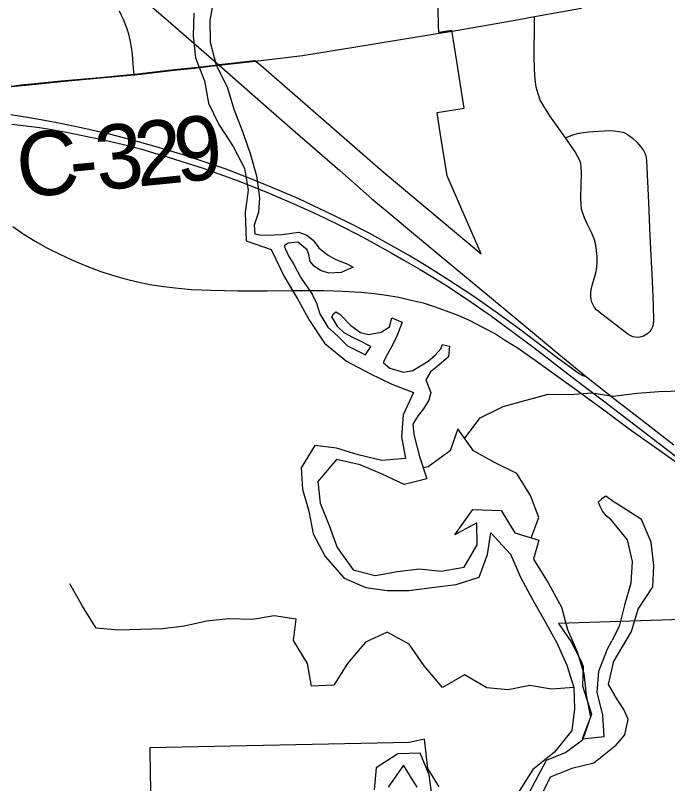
# Model space of a CAD drawing. Extents: x -6.4 to 34, y -4.2 to 22.
# Drawn here: x 4.489 to 5.066, y 17.606 to 18.286 of the extents above; entities that cross this region are included whole.
import ezdxf

# ---------------------------------------------------------------- set-up
doc = ezdxf.new("R2010")
doc.units = 0
for name, color, linetype in [('GM_X_Corporation', 7, 'Continuous'), ('GM_X_County_Road', 7, 'Continuous'), ('GM_X_County_Road_Text', 7, 'Continuous'), ('GM_X_Interchange_Ramps', 7, 'Continuous'), ('GM_X_Major_River', 7, 'Continuous'), ('GM_X_Minor_River', 7, 'Continuous'), ('GM_X_State_Route', 7, 'Continuous'), ('GM_X_Township_Road', 7, 'Continuous')]:
    doc.layers.add(name, color=color, linetype=linetype)

msp = doc.modelspace()

# ---------------------------------------------------------------- linework, layer by layer
at = {"layer": 'GM_X_Corporation'}
for points in [[(4.48506, 18.22318), (4.49382, 18.22417), (4.5149, 18.22629), (4.52916, 18.22763), (4.56388, 18.23083), (4.5937, 18.23365), (4.59436, 18.23371), (4.62916, 18.23774), (4.64724, 18.23961), (4.66596, 18.24174), (4.66901, 18.24211), (4.70069, 18.24566), (4.7064, 18.24128), (4.81426, 18.1471), (4.86666, 18.10342), (4.90117, 18.07465), (4.87091, 18.14362), (4.86521, 18.17986), (4.86209, 18.19978), (4.88602, 18.2036), (4.8825, 18.22601), (4.88132, 18.23356), (4.87661, 18.26351), (4.87515, 18.27234), (4.86948, 18.27132), (4.86354, 18.27045), (4.86347, 18.27676), (4.86282, 18.30664)], [(5.09729, 17.75149), (4.96968, 17.74738), (4.98078, 17.73099), (4.98912, 17.71503), (4.99128, 17.70933), (4.99082, 17.69215), (4.99887, 17.66701), (4.99089, 17.64415), (4.99042, 17.64379), (4.97618, 17.63304), (4.95872, 17.62611), (4.94349, 17.59773)], [(4.86379, 17.6026), (4.85389, 17.6191), (4.85082, 17.64485), (4.83992, 17.64244), (4.83759, 17.64193), (4.60765, 17.63721), (4.60768, 17.63599), (4.60811, 17.61377), (4.60858, 17.59005)]]:
    msp.add_lwpolyline(points, dxfattribs=at)
at = {"layer": 'GM_X_County_Road'}
for points in [[(4.87535, 18.27179), (4.93128, 18.28156), (4.94833, 18.28464), (4.98994, 18.29219)], [(4.70089, 18.24511), (4.74295, 18.25028), (4.79019, 18.25779), (4.86392, 18.26993)], [(4.86392, 18.26993), (4.86968, 18.27076), (4.87535, 18.27179)], [(4.64744, 18.23906), (4.66615, 18.24119), (4.66921, 18.24155), (4.70089, 18.24511)], [(4.5939, 18.23309), (4.59455, 18.23316), (4.62936, 18.23718), (4.64744, 18.23906)], [(4.49803, 18.22402), (4.5151, 18.22574), (4.52935, 18.22707), (4.56408, 18.23027), (4.5939, 18.23309)], [(4.48526, 18.22262), (4.49402, 18.22362), (4.49803, 18.22402)]]:
    msp.add_lwpolyline(points, dxfattribs=at)
at = {"layer": 'GM_X_Interchange_Ramps'}
for points in [[(4.5939, 18.23309), (4.59338, 18.2389), (4.59227, 18.25121), (4.59138, 18.25761), (4.59032, 18.2637), (4.58909, 18.26913), (4.58761, 18.2739), (4.58605, 18.27818), (4.58441, 18.28197), (4.58276, 18.28554), (4.58088, 18.28929)], [(4.99428, 17.96579), (4.99122, 17.96667), (4.98955, 17.96737), (4.98796, 17.96827), (4.96968, 17.9815), (4.93518, 18.00788), (4.91354, 18.02355), (4.89366, 18.0374), (4.87351, 18.05084), (4.85377, 18.06322), (4.83692, 18.07335), (4.81982, 18.08299), (4.80181, 18.09279), (4.78405, 18.10201), (4.76515, 18.11132), (4.73958, 18.12318), (4.71672, 18.1329), (4.69723, 18.14097), (4.67437, 18.14971), (4.65686, 18.15589), (4.63717, 18.16227), (4.61336, 18.16943), (4.59124, 18.17564), (4.57199, 18.18057), (4.54848, 18.18581), (4.5257, 18.1906), (4.5049, 18.1944), (4.48467, 18.19754)], [(4.48554, 18.18936), (4.49837, 18.18799), (4.50995, 18.18639), (4.52101, 18.1846), (4.53384, 18.18224), (4.54665, 18.17973), (4.56675, 18.17554), (4.58312, 18.17172), (4.59938, 18.16742), (4.61014, 18.16432), (4.62325, 18.16039), (4.63513, 18.1567), (4.65586, 18.15003), (4.66469, 18.147), (4.67698, 18.14254), (4.68744, 18.13852), (4.70825, 18.13025), (4.73519, 18.11888), (4.75225, 18.11129), (4.76239, 18.10654), (4.77691, 18.09937), (4.79183, 18.09166), (4.80337, 18.08553), (4.82134, 18.07558), (4.83265, 18.06907), (4.8472, 18.06068), (4.85846, 18.05403), (4.869, 18.0474), (4.88816, 18.03462), (4.91012, 18.01933), (4.92376, 18.00953), (4.94769, 17.99167), (4.9817, 17.96551), (5.00939, 17.94442), (5.0272, 17.93086), (5.08129, 17.88937)]]:
    msp.add_lwpolyline(points, dxfattribs=at)
at = {"layer": 'GM_X_Major_River'}
for p, q in [((5.00758, 17.85731), (5.00462, 17.85468)), ((5.00462, 17.85468), (5.00643, 17.85049)), ((5.01153, 17.85994), (5.00758, 17.85731)), ((5.01879, 17.85477), (5.01153, 17.85994)), ((5.00643, 17.85049), (5.00856, 17.84645)), ((5.00856, 17.84645), (5.01086, 17.84349)), ((5.01086, 17.84349), (5.01454, 17.84082)), ((5.01454, 17.84082), (5.01862, 17.83591))]:
    msp.add_line(p, q, dxfattribs=at)
for points in [[(4.6645, 18.30086), (4.66075, 18.28104), (4.66114, 18.26207), (4.66649, 18.24168), (4.67636, 18.22253), (4.68208, 18.20253), (4.68968, 18.18295), (4.69653, 18.16336), (4.70224, 18.14373), (4.70493, 18.12405)], [(4.64659, 18.28757), (4.64625, 18.26744), (4.64817, 18.24812), (4.65617, 18.22779), (4.65961, 18.20812), (4.66872, 18.18896), (4.68163, 18.16949), (4.6915, 18.15034), (4.69493, 18.13105), (4.69231, 18.11125), (4.69295, 18.08619), (4.71519, 18.07844), (4.72682, 18.05466), (4.7386, 18.0348), (4.74923, 18.01566), (4.76253, 17.99544), (4.7818, 17.97953), (4.80249, 17.96858), (4.82201, 17.95913), (4.8411, 17.95194), (4.83204, 17.93201), (4.83055, 17.91262), (4.83398, 17.89333), (4.81318, 17.89175)], [(4.70493, 18.12405), (4.70405, 18.1115), (4.70012, 18.10003), (4.70066, 18.09245), (4.70522, 18.09141), (4.71129, 18.09116), (4.72454, 18.09182), (4.73965, 18.09366), (4.7469, 18.09116), (4.7523, 18.08672), (4.75736, 18.07999), (4.76507, 18.0737), (4.77235, 18.06968), (4.78305, 18.06535), (4.78765, 18.0628), (4.77714, 18.05801), (4.76617, 18.0574), (4.75892, 18.0599), (4.75316, 18.06358), (4.74966, 18.06768), (4.74839, 18.07411), (4.74717, 18.07826), (4.7387, 18.08491), (4.73038, 18.08397), (4.72664, 18.08162), (4.72745, 18.07936), (4.73061, 18.07297), (4.73532, 18.0651), (4.74124, 18.05383), (4.7514, 18.03887), (4.75535, 18.03098), (4.7582, 18.02155), (4.76527, 18.00955), (4.77414, 18.00176), (4.78265, 17.99322), (4.78916, 17.98994), (4.79873, 17.98521), (4.8035, 17.99252), (4.79316, 17.99799), (4.78743, 18.00053), (4.77977, 18.00454), (4.77435, 18.01012), (4.772, 18.01349), (4.76886, 18.01874), (4.77032, 18.02143), (4.77256, 18.02337), (4.77601, 18.02117), (4.78569, 18.01112), (4.79416, 18.00485), (4.80139, 18.00311), (4.81271, 18.00525), (4.81981, 18.00995), (4.82192, 18.01797), (4.83109, 18.01399), (4.82715, 18.00328), (4.82352, 17.99561), (4.81841, 17.98638), (4.81441, 17.97833), (4.82019, 17.97352), (4.83239, 17.96998), (4.84069, 17.9713), (4.85416, 17.97955), (4.86049, 17.98501), (4.8653, 17.99042), (4.86674, 17.99425), (4.87321, 17.99287), (4.87227, 17.98336), (4.86371, 17.97596), (4.85625, 17.97011), (4.85223, 17.96319), (4.85663, 17.95189), (4.85488, 17.94502), (4.85011, 17.93733), (4.84531, 17.93153), (4.84054, 17.92384), (4.84149, 17.91475)], [(4.84149, 17.91475), (4.84645, 17.89511), (4.85292, 17.87551), (4.83294, 17.87053), (4.81343, 17.8796), (4.79393, 17.88792), (4.77301, 17.8924), (4.75636, 17.87307), (4.75865, 17.85376), (4.76664, 17.83419), (4.77349, 17.81459), (4.78792, 17.79478), (4.80734, 17.78988), (4.82697, 17.79333), (4.84624, 17.79564), (4.8656, 17.79378), (4.88599, 17.79725), (4.8977, 17.81686), (4.89729, 17.83659), (4.87781, 17.82593), (4.89361, 17.84839), (4.91876, 17.8474), (4.931, 17.82772), (4.95217, 17.82106), (4.94759, 17.80426), (4.96053, 17.78327), (4.97234, 17.76189), (4.97768, 17.74188), (4.98604, 17.72232), (4.99212, 17.70308), (4.99404, 17.68376), (4.99785, 17.66448), (4.99067, 17.64535), (5.00995, 17.64728), (5.00879, 17.66662), (5.00384, 17.68625), (5.00534, 17.70526), (5.01289, 17.72479), (5.01691, 17.73209)], [(4.81318, 17.89175), (4.79224, 17.89661), (4.77317, 17.90266), (4.7538, 17.9049), (4.74171, 17.88529), (4.74286, 17.86633), (4.74857, 17.84671), (4.7524, 17.82667), (4.76304, 17.80678), (4.77973, 17.78739), (4.79885, 17.77907), (4.81785, 17.77643), (4.83717, 17.77647), (4.85983, 17.77961), (4.87911, 17.78192), (4.89943, 17.78843), (4.90659, 17.80832), (4.9096, 17.82774), (4.92704, 17.80876), (4.9358, 17.78844), (4.94644, 17.76855), (4.95744, 17.74942), (4.96807, 17.73029), (4.97682, 17.71035), (4.98329, 17.69075), (4.98368, 17.67178), (4.98143, 17.65275), (4.96592, 17.63343), (4.94691, 17.61822), (4.93481, 17.59898)], [(5.01807, 17.71275), (5.03435, 17.74037), (5.04015, 17.76009), (5.05315, 17.77978), (5.05403, 17.79877), (5.05151, 17.81929), (5.04293, 17.83946), (5.02332, 17.85209), (5.01879, 17.85477)], [(5.01862, 17.83591), (5.03032, 17.82129), (5.03474, 17.80228), (5.03348, 17.78291), (5.02806, 17.76357), (5.0234, 17.7446), (5.01691, 17.73209)], [(5.01807, 17.71275), (5.01354, 17.69329), (5.01904, 17.68392)], [(5.01997, 17.63914), (5.02823, 17.64885), (5.0312, 17.66251), (5.02747, 17.67127), (5.01904, 17.68392)], [(5.01997, 17.63914), (5.00097, 17.62355), (4.98137, 17.61896), (4.96221, 17.61134), (4.95202, 17.591)], [(4.85764, 17.59354), (4.85496, 17.61323), (4.84698, 17.63242), (4.82729, 17.632), (4.80823, 17.61944), (4.80636, 17.60004)], [(4.84457, 17.60237), (4.83242, 17.62185), (4.81881, 17.60258)]]:
    msp.add_lwpolyline(points, dxfattribs=at)
at = {"layer": 'GM_X_Minor_River'}
for points in [[(4.88653, 17.91128), (4.90029, 17.92929), (4.92053, 17.93959), (4.94088, 17.94496), (4.96047, 17.95031), (4.9798, 17.94997), (4.99908, 17.95152), (5.01788, 17.9486)], [(5.01788, 17.9486), (5.0391, 17.95116), (5.05841, 17.95259), (5.07924, 17.95325)], [(4.94532, 17.82322), (4.95213, 17.84118), (4.9449, 17.86077), (4.93275, 17.88025), (4.91361, 17.88971), (4.89445, 17.90031), (4.88041, 17.91975), (4.87362, 17.90025), (4.85421, 17.88617), (4.84973, 17.88517)], [(4.98329, 17.69075), (4.96324, 17.68918), (4.94423, 17.69257), (4.92499, 17.68875), (4.90602, 17.69024), (4.88645, 17.70197), (4.86699, 17.69055), (4.85067, 17.70994), (4.8374, 17.72902), (4.81785, 17.73961), (4.79872, 17.73085), (4.78282, 17.71191), (4.77072, 17.69267), (4.75103, 17.69187), (4.74721, 17.71191), (4.73504, 17.73215), (4.7373, 17.75118), (4.71791, 17.75418), (4.69867, 17.75074), (4.67781, 17.75143), (4.65815, 17.74949), (4.63817, 17.74489), (4.6189, 17.74258), (4.59959, 17.74217), (4.5799, 17.74137), (4.56016, 17.74323), (4.54801, 17.76271), (4.53699, 17.78259)]]:
    msp.add_lwpolyline(points, dxfattribs=at)
at = {"layer": 'GM_X_State_Route'}
for points in [[(4.59872, 18.30315), (4.62649, 18.27885), (4.65124, 18.25724), (4.66921, 18.24155), (4.70823, 18.20742), (4.73647, 18.18248), (4.77604, 18.14841), (4.8044, 18.12322), (4.81936, 18.1108), (4.83399, 18.09865), (4.86913, 18.06939), (4.90855, 18.03678), (4.94998, 18.00224), (4.96996, 17.98576), (4.99428, 17.96579), (5.01943, 17.94594), (5.04513, 17.92631), (5.07163, 17.90542)], [(4.4865, 18.09867), (4.49573, 18.09243), (4.50611, 18.08591), (4.5173, 18.0797), (4.52812, 18.0742), (4.53936, 18.06898), (4.55193, 18.06368), (4.56353, 18.05933), (4.57353, 18.056), (4.58604, 18.05241), (4.59687, 18.04977), (4.6078, 18.04754), (4.62003, 18.04558), (4.63296, 18.04406), (4.6447, 18.04307), (4.66205, 18.04233), (4.68565, 18.04184), (4.71175, 18.04184), (4.73387, 18.04218), (4.74766, 18.04217), (4.76172, 18.04216), (4.77856, 18.04169), (4.79447, 18.04066), (4.80669, 18.03944), (4.81723, 18.03805), (4.82834, 18.0362), (4.83926, 18.03368), (4.84971, 18.03109), (4.86035, 18.02775), (4.87024, 18.02423), (4.88042, 18.02024), (4.89041, 18.0158), (4.9029, 18.0094), (4.91371, 18.00366), (4.92278, 17.99801), (4.93286, 17.99162), (4.94905, 17.98041), (4.98912, 17.95158), (5.00967, 17.93648), (5.0321, 17.91978), (5.05423, 17.90396), (5.07433, 17.88987)]]:
    msp.add_lwpolyline(points, dxfattribs=at)
at = {"layer": 'GM_X_Township_Road'}
msp.add_lwpolyline([(4.97587, 18.17725), (4.98215, 18.17996), (4.98643, 18.18115), (4.9914, 18.18204), (4.99656, 18.1826), (5.00074, 18.18293), (5.01444, 18.18376), (5.01888, 18.18362), (5.02329, 18.18302), (5.02641, 18.1823), (5.02885, 18.18133), (5.03168, 18.17976), (5.03517, 18.17697), (5.03883, 18.17347), (5.04215, 18.16965), (5.04471, 18.16601), (5.04595, 18.16373), (5.04686, 18.16125), (5.0472, 18.15972), (5.04751, 18.15693), (5.04935, 18.12012), (5.05055, 18.09032), (5.0524, 18.05062), (5.05349, 18.02886), (5.0537, 18.01514), (5.05352, 18.01254), (5.05303, 18.01058), (5.05197, 18.00813), (5.05044, 18.00597), (5.04861, 18.00408), (5.04645, 18.00254), (5.04469, 18.00162), (5.04275, 18.00099), (5.04011, 18.00067), (5.03748, 18.00074), (5.0355, 18.00116), (5.03363, 18.00193), (5.03087, 18.00361), (5.02582, 18.00735), (5.01404, 18.01642), (5.00662, 18.02216), (5.0033, 18.02512), (5.00159, 18.0271), (5.00018, 18.02931), (4.99912, 18.03172), (4.99842, 18.03424), (4.99807, 18.03683), (4.99808, 18.03943), (4.99862, 18.04325), (5.00003, 18.04874), (5.00253, 18.05767), (5.00342, 18.06247), (5.00389, 18.06733), (5.00389, 18.07221), (5.00337, 18.07769), (5.0023, 18.08372), (5.0011, 18.08779), (4.99905, 18.09291), (4.99498, 18.10125), (4.99254, 18.10634), (4.99098, 18.1105), (4.99003, 18.11422), (4.98956, 18.11802), (4.98942, 18.12431), (4.98993, 18.14666), (4.98973, 18.15155), (4.98927, 18.15448), (4.98837, 18.15731), (4.98684, 18.16059), (4.98435, 18.1648), (4.97669, 18.17608), (4.97587, 18.17725), (4.96202, 18.19692), (4.95645, 18.20524), (4.95341, 18.21076), (4.95143, 18.21613), (4.94995, 18.22226), (4.94898, 18.22911), (4.9483, 18.23784), (4.94792, 18.24969), (4.94833, 18.27877), (4.94833, 18.28464)], dxfattribs=at)

# ---------------------------------------------------------------- texts
at = {"layer": 'GM_X_County_Road_Text'}
for s, rotation, p in [('2', 5.62839, (4.59702, 18.13408)), ('9', 6.04177, (4.63229, 18.13756)), ('3', 5.51951, (4.56206, 18.13071)), ('C', 5.48224, (4.49234, 18.12401)), ('-', 5.49062, (4.53881, 18.12847))]:
    msp.add_text(s, height=0.05682, rotation=rotation, dxfattribs=at).set_placement(p)

doc.saveas('drawing.dxf')
